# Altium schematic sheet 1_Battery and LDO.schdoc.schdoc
size 309 x 223 mm; Symbol: Sheet-Symbol-Custom; Device: Sheet-Symbol-Custom; @Page Count: 4; @Create Date: 2024-03-28; Drawn: Thomas Crisafulli; @Page No: 4; @Page Name: Battery and LDO; @Project Name: OhmmeterV3.0_Release; @Schematic Name: schematic; Page Size: A4; @Update Date: 2024-03-27
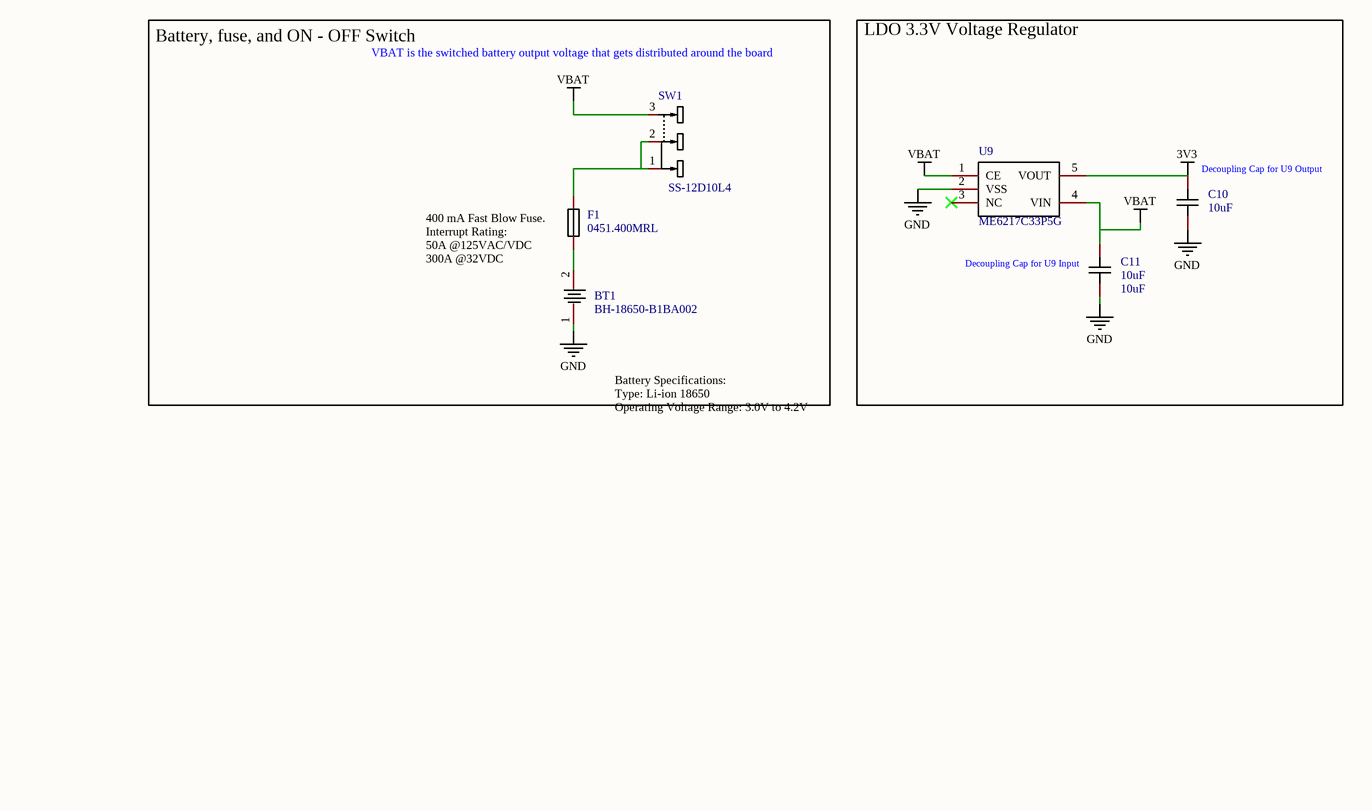
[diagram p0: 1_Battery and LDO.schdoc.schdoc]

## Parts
BT1  BH-18650-B1BA002  [BATTERY-SMD_18650-1S-L77.1-W20.7-1]
C10  10uF  [C0603]
C11  10uF  [C0603]
F1  0451.400MRL  [0451.400MRL]
SW1  SS-12D10L4  [SW-TH_SS-12D10L3]
U9  ME6217C33P5G  [SOT-89-5_L4.5-W2.5-P1.50-LS4.5-BR]

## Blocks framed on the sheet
Battery, fuse, and ON - OFF Switch: BT1 F1 SW1
LDO 3.3V Voltage Regulator: C10 C11 U9

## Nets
3V3: C10.2 U9.5(VOUT)
GND: BT1.1 C10.1 C11.1 U9.2(VSS)
VBAT: C11.2 SW1.3 U9.1(CE) U9.4(VIN)
NetBT1_2: BT1.2 F1.1
NetF1_2: F1.2 SW1.1 SW1.2

Not connected (* = marked no-connect by the designer): U9 3(NC)*

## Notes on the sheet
- VBAT is the switched battery output voltage that gets distributed around the board
- (near C10) Decoupling Cap for U9 Output
- 400 mA Fast Blow Fuse.
  Interrupt Rating:
  50A @125VAC/VDC
  300A @32VDC
- (near C11) Decoupling Cap for U9 Input
- Battery Specifications:
  Type: Li-ion 18650
  Operating Voltage Range: 3.0V to 4.2V

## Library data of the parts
BT1 = BH-18650-B1BA002: Manufacturer: MYOUNG(美阳); Add into BOM: yes
C10 C11 = CL10A106KP8NNNC: Manufacturer: SAMSUNG(三星); Add into BOM: yes; Tolerance: ±10%; Description: Capacitance: Tolerance:±10% Tolerance:±10% Voltage Rated: Temperature Coefficient:
F1 = 0451.400MRL: Add into BOM: yes; Description: 400 mA Fast Blow Fuse. Interrupt Rating: 50A @125VAC/VDC 300A @32VDC
SW1 = SS-12D10L4: Current Rating (DC):3A Voltage Rating (DC):125V Current Rating (AC):3A Voltage Rating (AC):125V Circuit:SPDT Mounting Style:Straight Mechanical Life:10000 Actuator Color:Black Actuator Style:Rectangular columnar Pin Style:PCPin Operating Temperature:-40~; Manufacturer: XKB Connectivity(中国星坤); Add into BOM: yes; Current Rating (DC): 3A; Voltage Rating (DC): 125V; Circuit: SPDT; Mechanical Life: 10000; Actuator Color: Black; Pin Style: PCPin; Switch Length: 13mm; Switch Width: 6.8mm; Switch Height: 6.4mm
U9 = ME6217C33P5G: Manufacturer: MICRONE(南京微盟); Add into BOM: yes; Output Polarity: Positive; Number of Outputs: 1; Maximum Input Voltage: 6.5V; Output Voltage: 3.3V~3.3V; Dropout Voltage: 180mV@(300mA); Output Current: 800mA; Power Supply Rejection Ratio (PRSS): 65dB@(1kHz); Description: Output Type: Output Polarity:Positive Number of Outputs:1 Maximum Input Voltage:6.5V Output Voltage:3.3V~3.3V Output Voltage:3.3V~3.3V Dropout Voltage:180mV@(300mA) Output Current:800mA Power Supply Rejection Ratio (PRSS):65dB@(1kHz)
